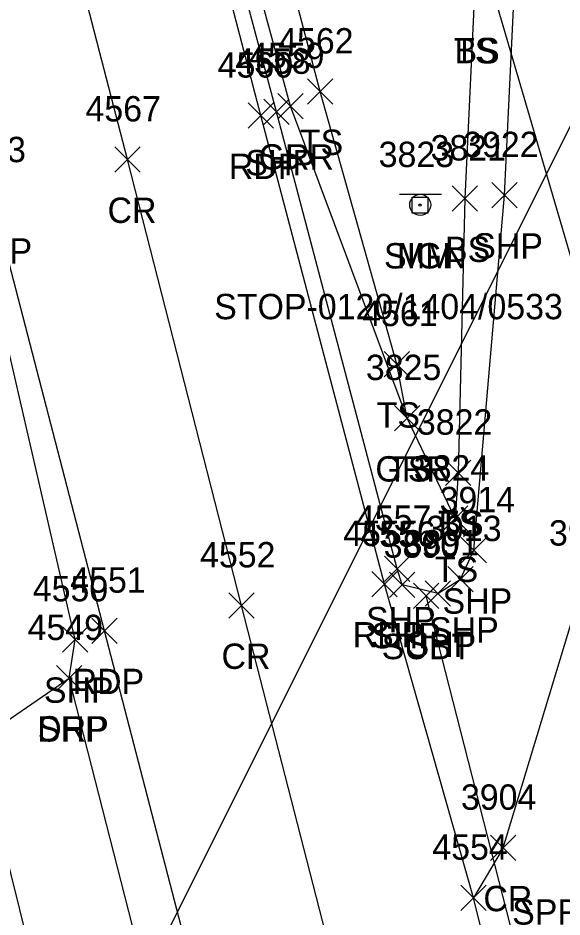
# Model space of a CAD drawing. Extents: x 1601151 to 1602912, y 499508 to 501770.
# Drawn here: x 1601646.6 to 1601689.5, y 500341.3 to 500412.2 of the extents above; entities that cross this region are included whole.
import ezdxf

# ---------------------------------------------------------------- set-up
doc = ezdxf.new("R2010")
doc.units = 0
for name, color, linetype in [('DCP', 7, 'Continuous'), ('L_A', 7, 'Continuous'), ('L_I', 7, 'Continuous'), ('L_TIC', 7, 'Continuous'), ('LELB', 7, 'Continuous'), ('P_A', 7, 'Continuous'), ('P_I', 7, 'Continuous'), ('P_TIC', 7, 'Continuous'), ('PET', 7, 'Continuous'), ('PRC', 7, 'Continuous'), ('PSP', 7, 'Continuous'), ('R_A', 7, 'Continuous'), ('R_I', 7, 'Continuous'), ('R_TIC', 7, 'Continuous'), ('RDP', 7, 'Continuous'), ('RGR', 7, 'Continuous'), ('S_A', 7, 'Continuous'), ('S_C', 7, 'Continuous'), ('S_I', 7, 'Continuous'), ('SRM', 7, 'Continuous'), ('SSGN', 7, 'Continuous'), ('U_A', 7, 'Continuous'), ('U_I', 7, 'Continuous'), ('U_TIC', 7, 'Continuous'), ('UCO', 7, 'Continuous'), ('UT', 7, 'Continuous')]:
    doc.layers.add(name, color=color, linetype=linetype)

msp = doc.modelspace()

# ---------------------------------------------------------------- linework, layer by layer
at = {"layer": 'DCP'}
msp.add_lwpolyline([(1601681.865, 500421.833), (1601698.55, 500364.843)], dxfattribs=at)
at = {"layer": 'L_TIC'}
for points in [[(1601669.44, 500405.37), (1601671.44, 500407.37)], [(1601671.44, 500405.37), (1601669.44, 500407.37)], [(1601680.856, 500396.932), (1601682.856, 500398.932)], [(1601682.856, 500396.932), (1601680.856, 500398.932)], [(1601675.5, 500383.872), (1601677.5, 500385.872)], [(1601677.5, 500383.872), (1601675.5, 500385.872)], [(1601676.319, 500379.62), (1601678.319, 500381.62)], [(1601678.319, 500379.62), (1601676.319, 500381.62)], [(1601680.34, 500375.315), (1601682.34, 500377.315)], [(1601682.34, 500375.315), (1601680.34, 500377.315)], [(1601680.34, 500375.315), (1601682.34, 500377.315)], [(1601682.34, 500375.315), (1601680.34, 500377.315)], [(1601680.093, 500371.697), (1601682.093, 500373.697)], [(1601682.093, 500371.697), (1601680.093, 500373.697)]]:
    msp.add_lwpolyline(points, dxfattribs=at)
at = {"layer": 'LELB'}
for points in [[(1601676.5, 500384.872), (1601670.44, 500406.37), (1601660.93, 500442.547), (1601649.052, 500490.729), (1601634.54, 500542.998), (1601631.677, 500557.447), (1601631.6, 500563.017)], [(1601684.505, 500421.272), (1601683.713, 500421.231), (1601680.21, 500421.029), (1601682.605, 500413.597), (1601681.856, 500397.932), (1601681.34, 500376.315)], [(1601677.319, 500380.62), (1601676.5, 500384.872)], [(1601681.34, 500376.315), (1601681.093, 500372.697), (1601677.319, 500380.62)]]:
    msp.add_lwpolyline(points, dxfattribs=at)
at = {"layer": 'P_TIC'}
for points in [[(1601664.758, 500403.469), (1601666.758, 500405.469)], [(1601666.758, 500403.469), (1601664.758, 500405.469)], [(1601666.013, 500403.766), (1601668.013, 500405.766)], [(1601668.013, 500403.766), (1601666.013, 500405.766)], [(1601654.243, 500400.01), (1601656.243, 500402.01)], [(1601656.243, 500400.01), (1601654.243, 500402.01)], [(1601683.989, 500397.2), (1601685.989, 500399.2)], [(1601685.989, 500397.2), (1601683.989, 500399.2)], [(1601681.567, 500369.201), (1601683.567, 500371.201)], [(1601683.567, 500369.201), (1601681.567, 500371.201)], [(1601675.532, 500367.735), (1601677.532, 500369.735)], [(1601677.532, 500367.735), (1601675.532, 500369.735)], [(1601674.526, 500366.537), (1601676.526, 500368.537)], [(1601676.526, 500366.537), (1601674.526, 500368.537)], [(1601675.93, 500366.473), (1601677.93, 500368.473)], [(1601677.93, 500366.473), (1601675.93, 500368.473)], [(1601680.509, 500366.924), (1601682.509, 500368.924)], [(1601682.509, 500366.924), (1601680.509, 500368.924)], [(1601678.73, 500365.79), (1601680.73, 500367.79)], [(1601680.73, 500365.79), (1601678.73, 500367.79)], [(1601663.233, 500364.849), (1601665.233, 500366.849)], [(1601665.233, 500364.849), (1601663.233, 500366.849)], [(1601652.429, 500362.857), (1601654.429, 500364.857)], [(1601654.429, 500362.857), (1601652.429, 500364.857)], [(1601650.123, 500362.174), (1601652.123, 500364.174)], [(1601652.123, 500362.174), (1601650.123, 500364.174)], [(1601649.638, 500359.121), (1601651.638, 500361.121)], [(1601651.638, 500359.121), (1601649.638, 500361.121)], [(1601683.895, 500345.741), (1601685.895, 500347.741)], [(1601685.895, 500345.741), (1601683.895, 500347.741)], [(1601681.557, 500341.801), (1601683.557, 500343.801)], [(1601683.557, 500341.801), (1601681.557, 500343.801)]]:
    msp.add_lwpolyline(points, dxfattribs=at)
at = {"layer": 'PET'}
for points in [[(1601995.672, 499683.239), (1601967.438, 499723.891), (1601951.2, 499747.807), (1601928.383, 499780.817), (1601898.695, 499825.125), (1601866.225, 499874.785), (1601846.19, 499907.837), (1601823.764, 499946.631), (1601805.555, 499981.904), (1601788.872, 500017.294), (1601766.923, 500067.608), (1601755.39, 500098.806), (1601743.924, 500129.717), (1601726.447, 500185.711), (1601711.929, 500234.213), (1601699.419, 500278.305), (1601688.326, 500319.606), (1601682.557, 500342.801), (1601675.526, 500367.537), (1601665.758, 500404.469), (1601656.174, 500441.197), (1601643.947, 500489.359), (1601630.25, 500541.677)], [(1601976.032, 499671.31), (1601949.068, 499710.223), (1601932.497, 499734.587), (1601906.156, 499773.603), (1601879.172, 499813.541), (1601846.776, 499862.768), (1601825.901, 499896.892), (1601802.833, 499936.77), (1601785.078, 499971.146), (1601767.412, 500007.572), (1601745.411, 500058.715), (1601733.838, 500089.245), (1601721.798, 500122.71), (1601703.993, 500178.986), (1601689.714, 500228.268), (1601677.577, 500272.249), (1601666.12, 500315.053), (1601653.429, 500363.857), (1601644.592, 500397.799), (1601635.031, 500435.309), (1601622.916, 500483.995), (1601609.643, 500536.455)]]:
    msp.add_lwpolyline(points, dxfattribs=at)
at = {"layer": 'PRC'}
for points in [[(1601985.389, 499677.473), (1601958.565, 499716.671), (1601942.322, 499739.604), (1601916.264, 499778.512), (1601888.678, 499819.151), (1601856.543, 499869.05), (1601836.005, 499902.112), (1601813.365, 499942.521), (1601794.976, 499977.026), (1601778.265, 500012.715), (1601755.571, 500062.845), (1601744.487, 500093.78), (1601732.766, 500126.074), (1601715.372, 500182.363), (1601700.572, 500231.277), (1601688.367, 500275.568), (1601676.784, 500317.033), (1601664.233, 500365.849), (1601655.243, 500401.01), (1601645.633, 500438.144), (1601632.995, 500486.745), (1601619.53, 500538.875)], [(1601684.895, 500346.741), (1601691.195, 500367.57), (1601696.665, 500397.034), (1601694.847, 500422.857), (1601706.331, 500482.734), (1601717.449, 500499.11), (1601732.264, 500510.562), (1601765.35, 500515.922), (1601787.118, 500516.513), (1601817.681, 500506.119)], [(1601684.895, 500346.741), (1601682.557, 500342.801)]]:
    msp.add_lwpolyline(points, dxfattribs=at)
at = {"layer": 'PSP'}
for points in [[(1601676.93, 500367.473), (1601676.532, 500368.735), (1601667.013, 500404.766), (1601657.278, 500441.189), (1601645.244, 500489.646), (1601631.9, 500541.89)], [(1601687.75, 500227.801), (1601675.974, 500271.579), (1601664.353, 500314.612), (1601659.493, 500332.056), (1601657.413, 500333.692), (1601650.638, 500360.121), (1601651.123, 500363.174), (1601643.244, 500397.341), (1601633.675, 500434.789), (1601621.752, 500483.668), (1601608.777, 500536.075)], [(1601679.73, 500366.79), (1601681.509, 500367.924), (1601682.567, 500370.201), (1601684.989, 500398.2), (1601686.167, 500422.736), (1601697.893, 500484.96), (1601711.788, 500503.552), (1601729.212, 500518.485), (1601766.415, 500526.339), (1601787.762, 500526.588), (1601817.713, 500516.862)], [(1601679.73, 500366.79), (1601676.93, 500367.473)]]:
    msp.add_lwpolyline(points, dxfattribs=at)
at = {"layer": 'R_TIC'}
for points in [[(1601667.111, 500404.213), (1601669.111, 500406.213)], [(1601669.111, 500404.213), (1601667.111, 500406.213)], [(1601676.319, 500379.62), (1601678.319, 500381.62)], [(1601678.319, 500379.62), (1601676.319, 500381.62)], [(1601649.638, 500359.121), (1601651.638, 500361.121)], [(1601651.638, 500359.121), (1601649.638, 500361.121)]]:
    msp.add_lwpolyline(points, dxfattribs=at)
at = {"layer": 'RDP'}
msp.add_lwpolyline([(1601607.551, 500346.375), (1601610.142, 500355.266), (1601627.005, 500351.58), (1601642.275, 500354.375), (1601650.638, 500360.121)], dxfattribs=at)
at = {"layer": 'RGR'}
msp.add_lwpolyline([(1601677.319, 500380.62), (1601668.111, 500405.213), (1601658.23, 500441.579), (1601646.231, 500489.648), (1601632.914, 500542.211)], dxfattribs=at)
at = {"layer": 'SRM'}
msp.add_lwpolyline([(1601677.7, 500398.043), (1601678.95, 500398.043), (1601678.95, 500396.793), (1601677.7, 500396.793)], close=True, dxfattribs=at)
msp.add_circle((1601678.325, 500397.418), 0.0833, dxfattribs=at)
at = {"layer": 'SSGN'}
for p, q in [((1601676.698, 500398.271), (1601680.032, 500398.271)), ((1601678.345, 500397.438), (1601678.345, 500397.438))]:
    msp.add_line(p, q, dxfattribs=at)
msp.add_circle((1601678.345, 500397.438), 0.833, dxfattribs=at)
at = {"layer": 'U_TIC'}
for points in [[(1601677.81, 500365.615), (1601679.81, 500367.615)], [(1601679.81, 500365.615), (1601677.81, 500367.615)]]:
    msp.add_lwpolyline(points, dxfattribs=at)
at = {"layer": 'UCO'}
for points in [[(1601595.966, 500546.616), (1601650.892, 500325.105)], [(1601727.82, 500478.911), (1601650.892, 500325.105)]]:
    msp.add_lwpolyline(points, dxfattribs=at)
at = {"layer": 'UT'}
msp.add_lwpolyline([(1601700.451, 500298.64), (1601690.61, 500320.424), (1601678.81, 500366.615)], dxfattribs=at)

# ---------------------------------------------------------------- texts
at = {"layer": 'L_A'}
for s, p in [('TS', (1601681.014, 500408.597)), ('TS', (1601681.014, 500408.597)), ('BS', (1601681.046, 500408.597)), ('TS', (1601668.85, 500401.37)), ('BS', (1601680.297, 500392.932)), ('TS', (1601674.909, 500379.872)), ('TS', (1601675.729, 500375.62)), ('TS', (1601679.75, 500371.315)), ('BS', (1601679.781, 500371.315)), ('TS', (1601679.503, 500367.697))]:
    msp.add_text(s, height=2, dxfattribs=at).set_placement(p)
at = {"layer": 'L_I'}
for s, p in [('4562', (1601667.133, 500409.37)), ('3821', (1601679.163, 500400.932)), ('4561', (1601673.76, 500387.872)), ('3825', (1601674.059, 500383.62)), ('3822', (1601678.08, 500379.315)), ('3822', (1601678.08, 500379.315)), ('3824', (1601677.834, 500375.697))]:
    msp.add_text(s, height=2, dxfattribs=at).set_placement(p)
at = {"layer": 'P_A'}
for s, p in [('SHP', (1601664.548, 500399.766)), ('RDP', (1601663.247, 500399.469)), ('CR', (1601653.676, 500396.01)), ('RDP', (1601642.081, 500392.799)), ('SHP', (1601682.525, 500393.2)), ('SHP', (1601680.103, 500365.201)), ('SHP', (1601674.068, 500363.735)), ('SHP', (1601679.044, 500362.924)), ('RDP', (1601673.014, 500362.537)), ('SHP', (1601674.465, 500362.473)), ('SHP', (1601677.266, 500361.79)), ('CR', (1601662.666, 500360.849)), ('RDP', (1601650.918, 500358.857)), ('SHP', (1601648.658, 500358.174)), ('SHP', (1601648.173, 500355.121)), ('CR', (1601683.328, 500341.741))]:
    msp.add_text(s, height=2, dxfattribs=at).set_placement(p)
at = {"layer": 'P_I'}
for s, p in [('4558', (1601663.753, 500407.766)), ('4560', (1601662.365, 500407.469)), ('4567', (1601651.936, 500404.01)), ('3922', (1601681.729, 500401.2)), ('4563', (1601641.285, 500400.799)), ('3914', (1601679.874, 500373.201)), ('4557', (1601673.273, 500371.735)), ('3913', (1601678.816, 500370.924)), ('4555', (1601672.266, 500370.537)), ('4556', (1601673.615, 500370.473)), ('3912', (1601688.502, 500370.57)), ('3891', (1601677.038, 500369.79)), ('4552', (1601660.973, 500368.849)), ('4551', (1601650.737, 500366.857)), ('4550', (1601647.776, 500366.174)), ('4549', (1601647.37, 500363.121)), ('3904', (1601681.556, 500349.741)), ('4554', (1601679.298, 500345.801))]:
    msp.add_text(s, height=2, dxfattribs=at).set_placement(p)
at = {"layer": 'R_A'}
for s, p in [('GRR', (1601665.599, 500400.213)), ('GRR', (1601674.807, 500375.62)), ('DRP', (1601648.126, 500355.121))]:
    msp.add_text(s, height=2, dxfattribs=at).set_placement(p)
at = {"layer": 'R_I'}
for s, p in [('4559', (1601664.844, 500408.213)), ('3825', (1601674.059, 500383.62)), ('4549', (1601647.37, 500363.121))]:
    msp.add_text(s, height=2, dxfattribs=at).set_placement(p)
at = {"layer": 'S_A'}
for s, p in [('SIGN', (1601675.483, 500392.418)), ('MM', (1601676.514, 500392.418))]:
    msp.add_text(s, height=2, dxfattribs=at).set_placement(p)
at = {"layer": 'S_C'}
for s, p in [('STOP-0120/1404/0533', (1601662.09, 500388.418)), ('SPRING HOLLOW RD TH84', (1601685.598, 500340.687))]:
    msp.add_text(s, height=2, dxfattribs=at).set_placement(p)
at = {"layer": 'S_I'}
msp.add_text('3823', height=2, dxfattribs=at).set_placement((1601675.066, 500400.418))
msp.add_text('3823', height=2, dxfattribs=at).set_placement((1601675.066, 500400.418))
at = {"layer": 'U_A'}
msp.add_text('SUBT', height=2, dxfattribs=at).set_placement((1601675.306, 500361.615))
at = {"layer": 'U_I'}
msp.add_text('3890', height=2, dxfattribs=at).set_placement((1601675.463, 500369.615))

doc.saveas('drawing.dxf')
